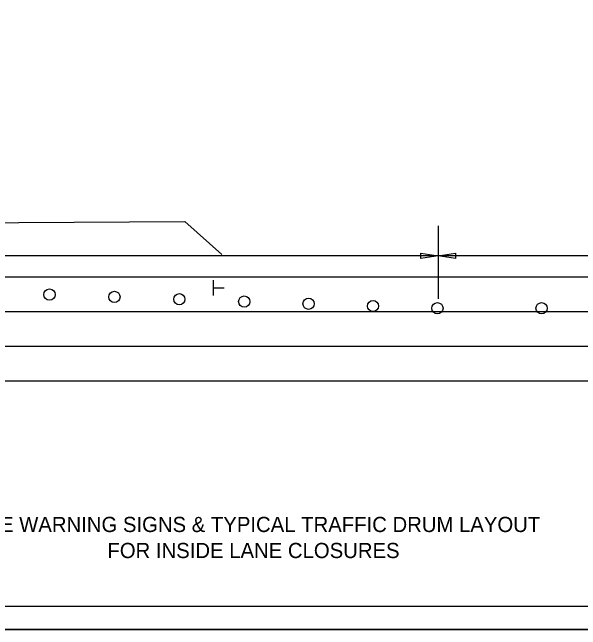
# Model space of a CAD drawing. Extents: x 1397271 to 1411271, y 376395 to 377888.
# Drawn here: x 1405137 to 1405825, y 376395 to 377141 of the extents above; entities that cross this region are included whole.
import ezdxf

# ---------------------------------------------------------------- set-up
doc = ezdxf.new("R2010")
doc.units = 0
for name, color, linetype in [('Default', 7, 'Continuous'), ('R_Border', 7, 'Continuous'), ('R_Border Notes', 7, 'Continuous'), ('R_MOT', 7, 'Continuous'), ('R_No Plot', 7, 'Continuous')]:
    doc.layers.add(name, color=color, linetype=linetype)

msp = doc.modelspace()

# ---------------------------------------------------------------- linework, layer by layer
at = {"layer": 'Default'}
for p, q in [((1405652.04, 376883.07), (1405652.04, 376794.66)), ((1405631.02, 376843.55), (1405631.02, 376849.86)), ((1405631.02, 376849.86), (1405652.04, 376846.71)), ((1405652.04, 376846.71), (1405673.06, 376849.86)), ((1405673.06, 376849.86), (1405673.06, 376843.55)), ((1405652.04, 376846.71), (1404634.83, 376846.71)), ((1405652.04, 376846.71), (1405631.02, 376843.55)), ((1405673.06, 376843.55), (1405652.04, 376846.71)), ((1406282.56, 376846.71), (1405652.04, 376846.71)), ((1404559.15, 376821.56), (1406315.82, 376821.56)), ((1404559.15, 376779.52), (1406315.82, 376779.52)), ((1404559.15, 376737.49), (1406315.82, 376737.49)), ((1404559.15, 376695.46), (1406315.82, 376695.46))]:
    msp.add_line(p, q, dxfattribs=at)
msp.add_lwpolyline([(1404824.33, 376851.81), (1404881.04, 376885.18), (1405068.8, 376885.18), (1405070.44, 376904.96), (1405077.03, 376886.83), (1405345.49, 376888.48), (1405390.34, 376848.32)], dxfattribs=at)
at = {"layer": 'R_Border'}
msp.add_line((1406571.3, 376422.47), (1404358, 376422.47), dxfattribs=at)
at = {"layer": 'R_MOT'}
for p, q in [((1405379.87, 376817.51), (1405379.87, 376798.59)), ((1405380.15, 376808.1), (1405393.07, 376808.1))]:
    msp.add_line(p, q, dxfattribs=at)
for centre in [(1405181.58, 376799.87), (1405260.16, 376797.05), (1405338.74, 376794.24), (1405417.32, 376791.43), (1405495.2, 376788.76), (1405573.18, 376786.08), (1405651.16, 376783.4), (1405777.16, 376783.4)]:
    msp.add_circle(centre, 6.8, dxfattribs=at)
at = {"layer": 'R_No Plot'}
msp.add_line((1404271.19, 376394.62), (1406604.57, 376394.62), dxfattribs=at)
for points in [[(1404271.14, 377887.98), (1406604.57, 377887.98), (1406604.57, 376394.59), (1404271.14, 376394.59)], [(1405995.47, 377860.72), (1405995.47, 377791.56), (1406245.6, 377791.56), (1406245.6, 377771.12), (1406408, 377771.12), (1406408, 377600.79), (1406571.3, 377600.79), (1406571.3, 376422.47), (1404358, 376422.47), (1404358, 377860.72)]]:
    msp.add_lwpolyline(points, close=True, dxfattribs=at)

# ---------------------------------------------------------------- texts
at = {"layer": 'R_Border Notes'}
for s, p in [('ADVANCE WARNING SIGNS & TYPICAL TRAFFIC DRUM LAYOUT', (1405019.25, 376512.66)), ('FOR INSIDE LANE CLOSURES', (1405251.69, 376481.16))]:
    msp.add_text(s, height=18.3753, dxfattribs=at).set_placement(p)

doc.saveas('drawing.dxf')
